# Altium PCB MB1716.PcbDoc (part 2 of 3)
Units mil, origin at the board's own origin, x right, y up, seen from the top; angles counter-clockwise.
Board outline 2806.95 x 1299.21 mil, 4 copper layers (Top Layer, M1, M2, Bottom Layer), stack 62.205 mil thick; 53 components, 45 nets, 298 pads, 399 vias.
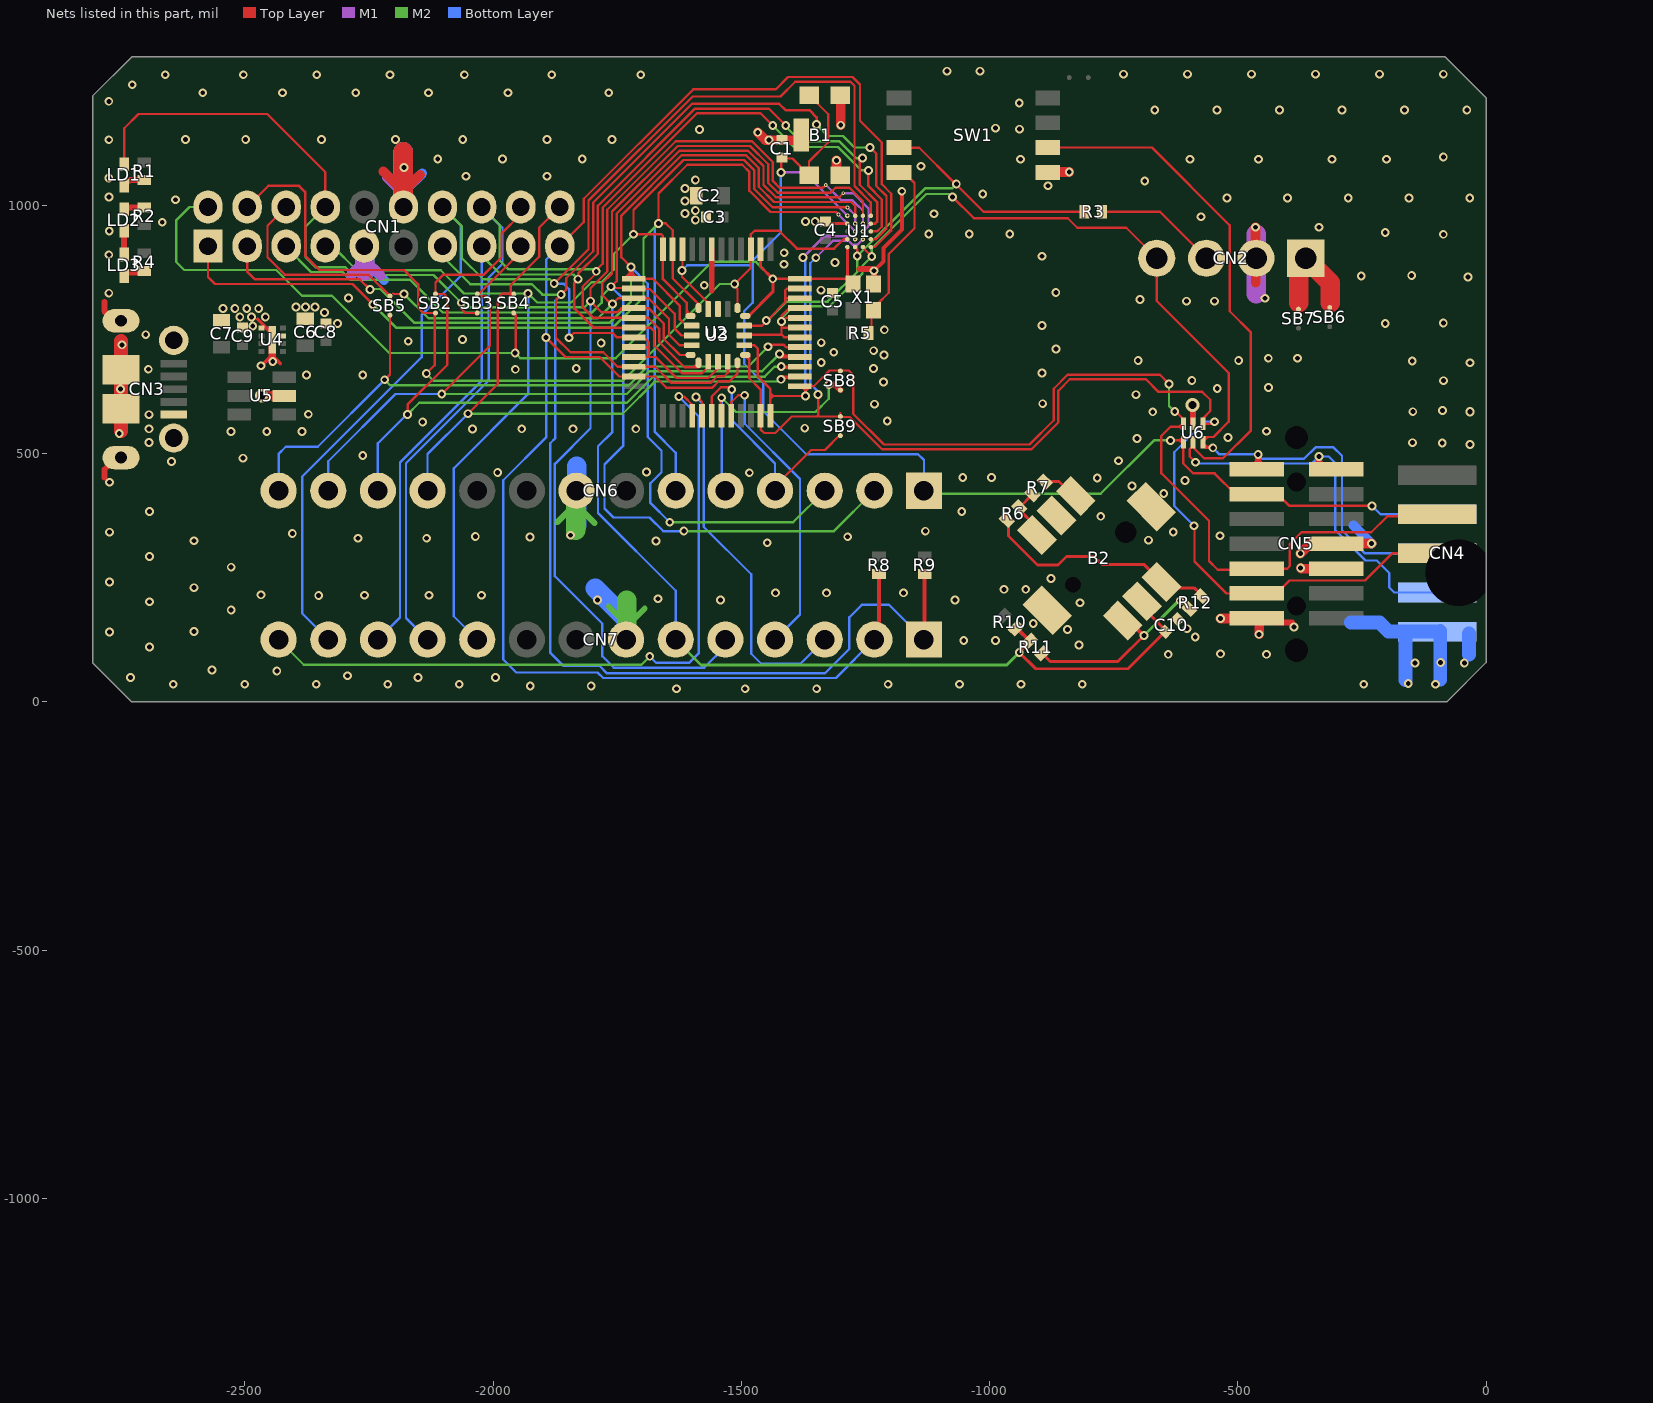
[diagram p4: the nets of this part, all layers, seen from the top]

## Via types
v1: diameter 17.72, hole 9.84, Top Layer to Bottom Layer, tented both sides, 357 vias
v2: diameter 27.56, hole 15.75, Top Layer to Bottom Layer, tented both sides, 31 vias
v3: diameter 7.87, hole 3.94, Top Layer to M1, tented both sides, 11 vias

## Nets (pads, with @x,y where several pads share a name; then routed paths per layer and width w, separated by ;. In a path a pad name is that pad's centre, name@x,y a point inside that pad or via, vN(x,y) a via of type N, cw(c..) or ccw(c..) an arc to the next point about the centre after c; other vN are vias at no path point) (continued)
GND: B1.2 B1.4 B1.5 B2.5 B2.7 B2.8 C1.1 C2.1 C3.1 C4.1 C5.1 C6.1 C7.1 C8.1 C9.1 C10.1 CN1.5 CN1.16 CN2.2 CN3.5 CN3.6 CN3.7 CN3.8 CN3.9 CN3.10 CN3.11 CN4.6 CN5.2 CN5.5 CN5.7 CN6.8 CN7.7 LD2.2 LD3.2 SW1.1 U1.D4 U2.7 U3.3 U4.3 U4.5 U4.9 U5.2 U6.2 X1.2 | length 3708.1
  Top Layer w5.91: C4.1@-1330.32,973.03 -1330.32,963.48 U1.D4@-1286.59,963.48 ; v2(-591.38,598.03) v2@-590.11,596.77
  Top Layer w7.28: -2474.29,770.83 U4.9@-2443.49,740.02 ; v1@-2463.23,680.59 -2443.13,700.69 ; -2449.1,701.81 -2429,681.71
  Top Layer w7.87: v1(-1232.95,868.5) -1214.09,887.36 -1214.09,914.29 -1176.85,951.54 v1(-1176.85,1028.7)
  Top Layer w11.81: -2783.27,806.1 -2783.27,787.15 CN3.9@-2763.04,766.92 ; -2783.19,451.5 -2783.19,468.23 -2761.86,489.56 CN3.8@-2761.86,494.61 ; LD3.2@-2744.06,901.34 LD2.2@-2744.06,949.25 ; -1559.76,828.7 U2.7@-1559.76,911.42 ; -1262.4,872.01 -1236.46,872.01 v1(-1232.95,868.5) X1.2@-1232.95,842.72 ; SW1.1@-882.75,1066.73 SW1.1@-881.93,1067.56 ; U6.2@-590.11,560.47 v2@-590.11,596.77 ; CN5.2@-422.67,160.16 -390.35,160.16
  Top Layer w15.75: v1@-2445.16,684.65 U4.9@-2445.16,721.85
  Top Layer w19.68: v2(-2466.1,616.97) -2465.47,616.34 U5.2@-2420.79,616.34 ; -2221.4,1068.43 -2189.8,1036.84 ; CN1.16@-2178.67,1030.17 -2147.07,1061.77 ; v1(-1467.01,1147.32) -1451.3,1131.61 C1.1@-1418.23,1131.61 -1389.6,1131.61 B1.5@-1379.48,1141.73 ; v1(-1308.31,1090.98) -1308.31,1068.59 B1.4@-1300.74,1061.02 ; B1.2@-1300.74,1222.44 -1299.84,1221.54 v1(-1299.84,1161.73) ; X1.2@-1233.94,841.73 X1.2@-1232.95,842.72 ; SW1.1@-881.93,1067.56 v1(-839.57,1067.56) ; v1(-534.68,168.19) -462.14,168.19 CN5.2@-461.95,168.38 ; v1(-464.17,956.06) -463.99,844.12 ; v1(-457.05,136.06) CN5.2@-457.05,168.38 ; v1(-374.12,298.76) -374.12,299.35 -355.09,318.38 CN5.7@-301.95,318.38 -297.82,314.25 -293.05,319.02 v1(-230.59,319.02) ; v1(-373.39,269.65) -372.12,268.38 CN5.5@-301.95,268.38
  Top Layer w27.56: v1@-2749.86,545.16 v1@-2749.86,727.24
  Top Layer w39.37: CN1.16@-2180.77,989.43 -2180.77,1108.21
  M1 w19.68: -2286.97,859.43 CN1.5@-2255.37,891.03 ; CN1.5@-2258.04,890.14 -2226.44,858.54 ; -2213.83,1056.42 CN1.16@-2182.23,1024.82 ; CN1.16@-2184.9,1023.93 -2153.3,1055.53
  M1 w39.37: -2258.88,868.82 CN1.5@-2258.88,917.48 ; CN1.16@-2181.4,997.48 -2181.4,1046.14 ; -463.25,822.56 -463.25,942.36
  M2 w11.81: -1870.87,361.89 CN6.8@-1837.87,394.88 ; CN6.8@-1828.31,392.99 -1795.31,360 ; -1767.36,192.32 CN7.7@-1734.37,159.33 ; CN7.7@-1727.68,154.96 -1694.68,187.95
  M2 w39.37: CN1.16@-2180.77,996.85 -2180.77,1046.28 ; -1833.74,345.67 CN6.8@-1833.74,425.83 ; CN7.7@-1730.74,124.96 -1730.74,205.12
  Bottom Layer w19.68: -2286.97,859.43 CN1.5@-2255.37,891.03 ; -2251.79,881.42 -2220.19,849.82 ; -2207.53,1053.43 CN1.16@-2175.94,1021.83 ; -2174.37,1033.25 -2142.77,1064.85 ; -267.07,355.51 v1(-230.59,319.02)
  Bottom Layer w27.56: -272.48,159.88 -214.69,159.88 -196.45,141.65 CN4.6@-162.36,141.65 ; v1@-162.36,43.98 CN4.6@-162.36,141.65 ; CN4.6@-162.36,142.01 CN4.6@-162.36,141.65 ; CN4.6@-98.43,141.65 CN4.6@-162.36,141.65 ; -92.2,44.88 CN4.6@-92.2,142.91 ; -34.33,95.04 CN4.6@-34.33,138.35
  Bottom Layer w39.37: -2258.88,868.82 CN1.5@-2258.88,917.48 ; CN1.16@-2180.77,989.43 -2180.77,1108.21 ; -1832.03,355.73 -1832.03,474.5 ; -1794.01,228.72 -1732.24,166.94 CN7.7@-1732.24,125.39
  other v1: -1630.79,26.5 -1492.4,26.5 -1348.39,26.5 -1925.39,31.89 -1802.6,31.89 -2644.48,35.55 -2500.47,35.55 -2356.46,35.55 -2212.45,35.55 -2068.44,35.55 -1204.38,35.55 -1060.37,35.55 -936.92,35.55 -813.47,35.55 -246.34,35.55 -101.85,35.55 -156.73,37.17 -2730.91,49.29 -2151.77,49.29 -1995.51,49.29 -2293.27,52.64 -2435.87,62.4 -2566.73,64.33 -143.03,78.35 -91.34,79.17 -43.74,78.35 -640.12,95.76 -442.12,95.76 -534.68,96.76 -2692.2,110.67 -820.12,114.76 -1052.12,123.76 -988.12,123.76 -585.81,130.99 -2772.91,140.79 -2602.68,141.5 -843.12,145.76 -602.19,147.53 -387.12,150.76 -912.12,157.76 -2527.83,184.8 -818.12,199.76 -2692.2,201.67 -1789.65,205.12 -1541.85,205.12 -1069.61,205.12 -1667.76,207.87 -2351.57,214.45 -2259.37,214.88 -2129.37,214.88 -2023.78,214.88 -2467.64,215.63 -1431.26,219.68 -1328.74,219.68 -1173.66,219.68 -971.12,226.76 -927.12,226.76 -2602.68,230.12 -2772.91,241.35 -876.12,248.76 -2527.83,271.38 -2692.2,292.66 -1447.99,320.51 -1671.97,323.82 -2602.68,324.65 -680.12,325.76 -2272.32,329.72 -2134.06,329.72 -1926.06,332.13 -1285.94,332.6 -2035.98,333.31 -536.12,334.76 -1844.53,335.67 -2404.68,339.21 -2772.91,341.92 -630.12,342.04 -1129.49,343.94 -776.12,373.76 -2692.2,383.66 -1056.12,383.76 -649.12,419.76 -713.12,434.76 -2772.91,442.48 -606.12,445.76 -783.12,450.76 -1054.12,451.76 -996.12,451.76 -1991.02,461.89 -1484.06,461.54 -1690.94,462.99 -2648.15,484.49 -740.12,485.76 -2503.86,490.94 -2262.76,496.18 -32.52,518.54 -148.07,522.2 -88.07,521.61 -2693.15,522.52 -703.12,530.76 -520,532.68 -2753.19,540.79 -2528.12,544.76 -2456.22,544.88 -2385.12,544.88 -442.2,545.24 -2693.15,550.04 -2041.85,549.68 -1942.44,550.04 -1839.33,550.04 -1712.68,550.04 -1372.32,551.38 -2142.05,563.98 -1206.18,565.67 -2693.15,578.62 -2372.4,579.53 -671.34,584.29 -32.52,584.06 -147.44,584.65 -32.52,585.2 -87.8,587.13 -1232.05,599.72 -893.12,600.76 -705.04,618.9 -2750.71,630.55 -541.38,631.57 -437.95,633.23 -1213.62,644.37 -85.63,647.09 -592.64,647.68 -2375.91,658.31 -2262.87,658.54 -894.21,662.56 -2694.76,670 -1955.43,669.88 -1832.8,671.57 -1234.09,671.57 -2467.83,677.05 -32.52,683.07 -1339.25,683.66 -2444.06,685.55 -148.62,686.61 -700.75,687.64 -498.27,687.64 -438.5,692.24 -379.53,692.24 -1212.72,698.58 -1314.06,704.33 -1233.58,707.48 -866.1,710.91 -2747.68,719.25 -1782.52,722.76 -1339.25,723.58 -2171.22,726.57 -2062.01,730.28 -2700,739.76 -1212.09,749.45 -2484.33,757.36 -894.21,758.18 -202.99,762.24 -2313.78,762.48 -85.98,763.43 -2510.43,775.35 -2486.81,775.35 -2459.06,775.35 -2339.92,784.57 -2544.41,792.56 -2520.43,792.56 -2496.46,792.56 -2472.48,792.56 -2397.52,795.63 -2378.37,795.63 -2359.21,795.63 -603.62,807.2 -547.2,807.2 -697.01,810.71 -445.28,813.07 -2291.42,813.66 -2774.29,823.35 -866.57,824.68 -1339.8,829.37 -1574.92,839.37 -36.34,855.63 -251.46,857.99 -149.8,859.17 -1414.21,881.54 -1311.57,885.32 -894.21,897.64 -2774.29,900.63 -1413.88,904.8 -1122.52,942.24 -1040.94,942.24 -959.37,942.24 -85.98,941.89 -202.99,945.43 -2773.46,948.82 -336.54,956.06 -2666.65,966.3 -1370.98,967.6 -1351.38,967.6 -1592.8,970.67 -574.09,977.36 -1112.24,983.23 -1613.78,983.74 -1592.8,989.8 -1613.78,1009.06 -2640.04,1011.57 -522.09,1015.16 -399.76,1015.16 -277.44,1015.16 -155.12,1015.16 -32.8,1015.16 -2773.86,1016.93 -1013.94,1022.83 -1613.78,1034.37 -882.09,1039.84 -687.56,1049.45 -1592.8,1051.02 -2774.29,1055.2 -2055.04,1058.82 -1891.46,1058.82 -2179.57,1076.61 -1138.43,1078.98 -937.83,1093.11 -596.54,1093.15 -458.27,1093.15 -310.55,1093.15 -200.63,1093.15 -2111.65,1093.43 -1981.1,1093.43 -1820.67,1093.43 -85.98,1097.87 -1444.65,1132.13 -2774.29,1132.48 -2619.76,1132.72 -2498.62,1132.72 -2346.06,1132.72 -2196.61,1132.72 -2061.34,1132.72 -1891.46,1132.72 -1760.87,1132.72 -1584.57,1153.23 -939.84,1153.74 -988.43,1155.75 -667.44,1192.44 -541.69,1192.44 -415.94,1192.44 -290.2,1192.44 -164.45,1192.44 -38.7,1192.44 -940.32,1206.38 -2774.29,1209.76 -2585.16,1227.13 -2424.68,1227.13 -2276.81,1227.13 -2130.55,1227.13 -1970.08,1227.13 -1767.17,1227.13 -2727.01,1243.11 -2660.67,1263.31 -2503.35,1263.31 -2355.47,1263.31 -2207.6,1263.31 -2058.19,1263.31 -1882.01,1263.31 -1702.68,1263.31 -730.08,1264.53 -601.26,1264.53 -472.44,1264.53 -343.62,1264.53 -214.8,1264.53 -85.98,1264.53 -1085.71,1270.55 -1019.53,1270.55
NetB2_1: B2.1 R11.2 R12.1 | length 419.5
  Top Layer w5.91: R11.2@-894.06,97.71 -878.12,81.76 -741.12,81.76 v1(-689.12,133.76) v1@-690.12,133.76 ; B2.1@-732.52,171.28 -732.52,170.76 B2.1@-727.12,170.76 ; v1(-616.12,203.76) -614.23,203.76 R12.1@-597.79,187.32
  Top Layer w7.87: B2.1@-727.12,170.76 v1@-690.12,133.76
  M2 w5.91: v1(-689.12,133.76) -619.12,203.76 v1(-616.12,203.76)
NetB2_3: B2.3 R6.1 R12.2 | length 455.7
  Top Layer w5.91: R6.1@-965.04,366.76 -962.12,363.84 -962.12,334.42 -903.45,275.76 -862.02,275.76 -845.12,292.66 -789.12,292.66 -772.87,276.41 -688.37,276.41 B2.3@-653.78,241.82 ; B2.3@-635.62,229.76 -587.87,229.76 R12.2@-578.21,220.1
NetB2_4: B2.4 R6.2 R7.1 | length 106.3
  Top Layer w5.91: R6.2@-942.52,389.27 -904.33,351.08 B2.4@-904.33,336.48 ; R6.2@-939.98,391.82 -914.12,417.68 R7.1@-914.12,418.76
NetB2_6: B2.6 R7.2 | length 67.2
  Top Layer w5.91: R7.2@-889.06,443.82 -860.17,443.82 B2.6@-833.12,416.76
NetCN2_1: CN2.1 SB6.2 SB7.1 | length 205.4
  Top Layer w7.87: SB6.2@-314.84,794.05 SB6.2@-314.84,794.25
  Top Layer w39.37: -377.28,804.37 -377.28,879.66 CN2.1@-363.25,893.7 -314.25,844.71 -314.25,803.9
NetCN2_3: CN2.3 R3.2 | length 252.3
  Top Layer w4.72: R3.2@-773.15,987.44 -656.99,987.44 CN2.3@-563.25,893.7
  M2 w4.72: CN2.3@-566.81,893.7 CN2.3@-563.25,893.7
NetLD1_1: LD1.1 R1.1 | length 45.1
  Top Layer w11.81: LD1.1@-2743.15,1039.8 -2731.73,1051.22 R1.1@-2702.75,1051.22
NetLD2_1: LD2.1 R2.1 | length 42.1
  Top Layer w7.87: LD2.1@-2743.15,992.22 LD2.1@-2739.11,996.26
  Top Layer w11.81: LD2.1@-2739.11,996.26 R2.1@-2702.75,996.26
NetLD3_1: LD3.1 R4.1 | length 44.7
  Top Layer w11.81: LD3.1@-2743.15,858.03 -2736.14,865.04 -2706.02,865.04 R4.1@-2702.75,868.31
NRST: B1.1 B1.3 C1.2 CN4.9 CN5.12 CN6.1 U1.E4 U2.10 U3.4 U6.4 | length 2900.1
  Top Layer w4.72: v1(-1619.61,869.06) -1619.61,856.26 -1566.93,803.58 U3.4@-1566.93,791.34 ; v1@-1618.81,869.06 U2.10@-1618.81,911.42 ; v1(-1420.51,1066.69) -1419.76,1067.44 -1419.76,1094.61 -1397.32,1094.61 B1.3@-1363.74,1061.02 -1363.74,1088.82 -1325.24,1127.32 -1325.24,1183.94 B1.1@-1363.74,1222.44 ; v1(-635.62,526.76) -617.57,526.76 ; -617.72,526.61 -617.57,526.76 ; -617.16,526.14 U6.4@-611.54,520.51 ; U6.4@-612.09,532.24 -617.57,526.76 ; v1(-229.68,394.84) -396.1,394.84 -419.64,418.38 CN5.12@-461.95,418.38 -504.8,418.38 -546.69,460.28 -589.65,460.28 -609.84,480.47 -609.84,523.03 U6.4@-609.8,523.07 -613.49,526.76 -617.57,526.76
  M1 w4.72: v1(-1420.51,1066.69) -1373.54,1066.69 v3(-1286.61,979.76)
  M2 w4.72: CN6.1@-1132.24,425.39 -1126.37,419.53 -776.14,419.53 -668.91,526.76 v1(-635.62,526.76)
  Bottom Layer w4.72: v1(-1619.61,869.06) -1609.06,879.61 -1481.93,879.61 ; -1477.32,875 -1481.93,879.61 ; -1477.32,884.21 -1481.93,879.61 ; v1(-1420.51,1066.69) -1420.51,945.87 -1477.15,889.23 -1477.15,879.61 ; CN6.1@-1132.24,425.39 -1132.24,486.96 -1144.25,498.98 -1369.25,498.98 -1455.91,585.63 -1455.91,642.68 -1494.37,681.14 -1494.37,787.13 -1477.15,804.35 -1477.15,879.61 ; v1(-229.68,394.84) -212.71,377.87 CN4.9@-98.43,377.87 ; -1481.93,879.61 -1477.15,879.61
OSC32K_EN: R5.1 SW1.8 X1.1 | length 379.5
  Top Layer w4.72: R5.1@-1237.91,745.28 -1237.91,777.36 -1231.97,783.31 -1226.57,783.31 -1226.57,800.79 -1203.07,824.29 -1203.07,902.36 -1151.18,954.25 -1151.18,1045.28 -1172.64,1066.73 SW1.8@-1182.75,1066.73
PA0: CN1.1 CN6.6 U1.C3 U2.11 U3.5 | length 2498.3
  Top Layer w4.72: CN1.1@-2574.47,918.11 -2574.47,855.65 -2560.51,841.69 -2283.5,841.69 v1(-2242.17,800.35) ; U3.5@-1586.61,793.31 -1586.61,801.3 -1638.5,853.19 U2.11@-1638.5,911.42 -1638.5,949.92 -1652.44,963.86 v1(-1667.01,963.86) -1667.01,1024.33 -1609.25,1082.09 -1498.46,1082.09 -1483.9,1067.52 -1483.9,1029.76 -1441.1,986.97 -1309.41,986.97 v3(-1304.61,982.17)
  M1 w4.72: v3(-1304.61,982.17) -1304.61,981.5 v3(-1270.84,947.74)
  M2 w4.72: v1(-2242.17,800.35) -2195.79,753.98 -1758.62,753.98 -1697.32,815.28 -1697.32,933.54 v1(-1667.01,963.86)
  Bottom Layer w4.72: v1(-1667.01,963.86) -1674.33,956.54 -1674.33,543.7 -1632.24,501.61 CN6.6@-1632.24,425.39
PA1: CN1.4 CN7.10 U1.D3 U2.12 U3.6 | length 2403.3
  Top Layer w4.72: CN1.4@-2338.25,918.11 CN1.4@-2338.07,918.11 ; -1609.43,787.05 U3.6@-1602.54,780.16 ; U3.6@-1602.36,777.56 -1608.82,777.56 -1610.24,778.98 -1610.24,803.7 -1658.18,851.65 U2.12@-1658.18,911.42 -1658.18,938.85 -1661.38,942.05 v1(-1717.44,942.05) -1717.44,990.75 -1616.65,1091.54 -1494.55,1091.54 -1474.45,1071.43 -1474.45,1033.68 -1437.19,996.42 -1286.5,996.42 v3(-1286.5,996.02)
  M1 w4.72: v3(-1286.5,996.02) -1270.84,980.37 v3(-1270.84,963.48)
  M2 w4.72: CN1.4@-2338.25,918.11 -2323.56,918.11 -2274.98,869.53 -2105.79,869.53 -2059.06,822.8 v1(-1929.68,822.8) -1911.38,804.49 -1842.95,804.49 -1801.94,845.5 -1782.26,845.5 -1757.17,870.59 -1757.17,902.32 v1(-1717.44,942.05)
  Bottom Layer w4.72: CN7.10@-2032.24,125.39 -2079.29,172.44 -2079.29,470.4 -1929.68,620 v1(-1929.68,822.8)
PA2: CN1.2 CN6.3 U1.E3 U2.13 U3.7 | length 2848.3
  Top Layer w4.72: CN1.2@-2495.73,918.11 -2495.73,867.14 -2479.72,851.14 -2268.98,851.14 v1(-2248.39,830.55) ; U2.13@-1734.51,854.06 -1725.31,863.25 ; U2.13@-1725.31,854.91 -1725.31,863.25 ; v1@-1725.31,873.54 -1725.31,863.25 ; -1722.36,866.4 -1722.26,866.3 ; -1721.33,867.24 -1722.26,866.3 ; U2.13@-1718.74,854.75 -1718.74,862.78 ; v1@-1718.74,873.38 -1718.74,862.78 ; U2.13@-1709.18,853.22 -1718.74,862.78 ; U3.7@-1600.39,757.87 -1611.12,757.87 -1624.43,771.18 -1624.43,798.56 -1678.23,852.36 U2.13@-1717.24,852.36 -1722.56,857.68 -1722.56,866.01 ; U1.E3@-1270.84,979.23 -1270.84,998.99 -1278.9,1007.05 -1434.46,1007.05 -1465,1037.59 -1465,1075.35 -1490.64,1100.98 -1620.57,1100.98 -1741.81,979.74 -1741.81,895.57 v1(-1722.56,876.32) -1722.56,866.01 ; -1725.31,863.25 -1722.56,866.01 ; -1722.56,866.01 -1722.26,866.3 ; -1722.26,866.3 -1718.74,862.78
  M2 w4.72: v1@-2248.39,831.73 -2227.01,831.73 -2158.7,763.43 -1765.75,763.43 -1722.56,806.61 v1(-1722.56,876.32) ; v1(-1644.25,361.81) -1395.82,361.81 CN6.3@-1332.24,425.39
  Bottom Layer w4.72: v1(-1722.56,876.32) -1688.74,842.49 -1688.74,533.46 -1661.1,505.83 -1661.1,462.67 -1683.31,440.47 -1683.31,400.87 v1(-1644.25,361.81)
PA3: CN1.3 CN6.2 U1.C2 U2.14 U3.8 | length 2868.6
  Top Layer w4.72: U3.8@-1600.39,738.19 -1620.51,738.19 -1634.57,752.24 -1634.57,781.69 -1684.57,831.69 -1716.26,831.69 U2.14@-1717.24,832.68 -1718.46,833.9 -1759.88,833.9 v1(-1762.44,836.46) -1751.26,847.64 -1751.26,983.65 -1624.48,1110.43 -1486.72,1110.43 -1455.55,1079.26 -1455.55,1041.5 -1430.54,1016.5 -1303.07,1016.5 v3(-1294.88,1024.68)
  M1 w4.72: v3(-1294.88,1024.68) -1274.84,1024.68 -1244.07,993.91 -1244.07,958.76 v3(-1255.09,947.74)
  M2 w4.72: CN1.3@-2416.99,918.11 -2416.99,916.27 -2366.74,866.02 -2303.82,866.02 -2288.43,850.63 -2167.64,850.63 -2101.46,784.45 -1801.19,784.45 -1781.66,803.98 -1781.66,817.24 v1(-1762.44,836.46) ; v1(-1615.98,344.06) -1313.58,344.06 CN6.2@-1232.24,425.39
  Bottom Layer w4.72: v1(-1762.44,836.46) -1737.76,811.77 -1737.76,516.22 -1775.74,478.23 -1775.74,389.66 -1757.62,371.54 -1685.04,371.54 -1657.56,344.06 v1(-1615.98,344.06)
PA4: B2.2 C10.2 CN1.13 CN7.6 R10.2 R11.1 SB5.1 U1.E2 U2.15 U3.9 | length 3935.3
  Top Layer w4.72: CN1.13@-2416.99,996.85 -2454.68,959.15 -2454.68,895.71 -2419.57,860.59 -2251.06,860.59 SB5.1@-2208.03,817.56 ; -2201.26,822.72 -2200.35,821.81 v1(-2179.41,821.81) ; U3.9@-1600.39,718.5 -1624.8,718.5 -1645.71,739.41 -1645.71,771.73 -1686.97,812.99 U2.15@-1717.24,812.99 -1748.7,812.99 v1(-1759.92,801.77) -1762.44,801.77 -1780.47,819.8 -1780.47,843.43 -1760.71,863.19 -1760.71,987.57 -1628.39,1119.88 -1482.81,1119.88 -1446.1,1083.17 -1446.1,1045.42 -1426.63,1025.94 -1320.35,1025.94 -1310.59,1035.71 -1282.28,1035.71 -1255.09,1008.52 U1.E2@-1255.09,979.23 ; B2.2@-693.55,192.19 B2.2@-693.55,209.73 ; C10.2@-650.19,143.99 C10.2@-650.19,148.84
  Top Layer w5.91: R10.2@-946.84,148.23 R10.2@-944.59,148.23 ; v1@-940.12,101.76 v1(-940.12,99.76) -907.12,66.76 -721.11,66.76 C10.2@-647.03,140.84 ; B2.2@-693.55,192.19 C10.2@-650.19,148.84 ; C10.2@-650.19,143.99 C10.2@-647.04,140.84 ; C10.2@-646.34,141.53 C10.2@-647.03,140.84
  Top Layer w7.87: R10.2@-944.59,148.23 R11.1@-919.12,122.76 v1@-940.12,101.76
  M2 w4.72: v1(-2179.41,821.81) -2130.47,772.87 -1788.82,772.87 v1(-1759.92,801.77)
  M2 w5.91: CN7.6@-1632.24,125.39 -1581.43,74.59 -965.29,74.59 v1(-940.12,99.76)
  Bottom Layer w4.72: v1(-1759.92,801.77) -1759.92,543.78 -1788.74,514.96 -1788.74,380.47 -1632.24,223.97 CN7.6@-1632.24,125.39
PA5: CN1.14 CN7.5 LD1.2 SB3.1 U1.D2 U2.16 U3.10 | length 3655.8
  Top Layer w4.72: LD1.2@-2743.15,1083.11 -2743.15,1155.75 -2714.76,1184.13 -2455.12,1184.13 -2338.25,1067.26 CN1.14@-2338.25,996.85 ; v1(-2064.25,803.98) -2064.25,792.09 -2055.55,783.39 SB3.1@-2036.89,783.39 ; -1745.35,790 -1745.23,790 ; U2.16@-1717.32,790 -1745.23,790 ; U3.10@-1602.36,698.82 -1623.98,698.82 -1656.38,731.22 -1656.38,762.28 -1687.4,793.31 U2.16@-1717.24,793.31 -1741.93,793.31 -1745.23,790 ; v3(-1330.12,1041.65) -1336.38,1035.39 -1422.72,1035.39 -1436.65,1049.33 -1436.65,1087.09 -1478.9,1129.33 -1632.31,1129.33 -1770.16,991.48 -1770.16,867.17 -1803.9,833.43 v1(-1803.9,807.2) -1781.54,784.84 -1750.39,784.84 -1745.23,790 ; SB3.1@-2036.89,783.39 -2034.49,780.98 SB3.1@-2032.09,783.39 SB3.1@-2036.89,783.39
  M1 w4.72: v3(-1330.12,1041.65) -1299.43,1010.97 -1276.71,1010.97 -1263.07,997.32 -1262.76,997.32 -1255.09,989.66 v3(-1255.09,963.48)
  M2 w4.72: CN1.14@-2338.25,996.85 -2378.15,956.95 -2378.15,895.79 -2357.83,875.47 -2297.6,875.47 -2282.2,860.08 -2120.35,860.08 v1(-2064.25,803.98) -2055.32,795.04 -1816.06,795.04 v1(-1803.9,807.2)
  Bottom Layer w4.72: v1(-1803.9,807.2) -1803.9,551.3 -1875.74,479.45 -1875.74,252.95 -1780,157.2 -1780,92.01 -1757.05,69.06 -1574.88,69.06 -1532.24,111.7 CN7.5@-1532.24,125.39
PA6: CN1.18 CN7.11 U1.C1 U2.17 U3.11 | length 2660.4
  Top Layer w4.72: -1596.1,674.31 U3.11@-1589.21,681.2 ; U3.11@-1586.61,683.07 -1586.61,674.17 -1614.61,674.17 -1665.83,725.39 -1665.83,751.61 -1687.83,773.62 U2.17@-1717.24,773.62 -1798.03,773.62 -1819.84,795.43 -1819.84,836.1 -1792.52,863.43 v1(-1792.52,867.36) -1792.52,869.88 -1779.61,882.8 -1779.61,995.4 -1589.33,1185.67 -1461.65,1185.67 v1(-1436.93,1160.94) ; v1(-1244.17,1070.71) -1244.17,1039.09 -1217.17,1012.09 -1217.17,957.32 -1226.75,947.74 U1.C1@-1239.35,947.74
  M2 w4.72: CN1.18@-2023.28,996.85 -1986.5,960.06 -1986.5,888.7 -1969.07,871.28 -1796.44,871.28 v1(-1792.52,867.36) ; v1(-1436.93,1160.94) -1393.82,1117.83 -1305.24,1117.83 -1258.11,1070.71 v1(-1244.17,1070.71)
  Bottom Layer w4.72: CN7.11@-2132.24,125.39 -2175.74,168.9 -2175.74,480.54 -2009.04,647.25 -2009.04,854.6 -1981.16,882.48 -1981.16,954.72 CN1.18@-2023.28,996.85
PA7: CN1.8 CN7.12 U1.D1 U2.18 U3.12 | length 2512.2
  Top Layer w4.72: U3.12@-1566.93,685.04 -1568.54,683.42 -1568.54,673.03 -1579.39,662.19 -1619.82,662.19 -1676.06,718.43 -1676.06,746.97 -1683.03,753.94 U2.18@-1717.24,753.94 -1798.23,753.94 -1836.51,792.22 -1836.51,844 v1(-1828.98,851.54) -1828.98,862.95 -1789.06,902.87 -1789.06,999.31 -1593.25,1195.12 -1444.92,1195.12 v1(-1410.75,1160.94) v1@-1410.75,1158.98 ; v1(-1256.14,1095.39) -1259.92,1095.39 -1261.5,1093.82 -1261.5,1041.73 -1226.61,1006.85 -1226.61,967.52 -1230.65,963.48 U1.D1@-1239.35,963.48
  M2 w4.72: CN1.8@-2023.28,918.11 -2023.28,899.5 -1984.65,860.87 -1838.31,860.87 v1(-1828.98,851.54) ; v1@-1410.75,1158.98 -1381.38,1129.61 -1303.19,1129.61 -1268.98,1095.39 v1(-1256.14,1095.39)
  Bottom Layer w4.72: CN7.12@-2232.24,125.39 -2187.68,169.96 -2187.68,481.97 -2023.28,646.36 CN1.8@-2023.28,918.11
PA8: CN7.14 U2.28 | length 1505.1
  Top Layer w4.72: v1(-1626.06,615.28) -1615.87,615.28 -1599.13,598.54 U2.28@-1599.13,576.77 ; U2.28@-1602.67,573.5 -1602.67,601.53
  M2 w4.72: CN7.14@-2432.24,125.39 -2381.81,74.96 -1701.5,74.96 v1(-1684.72,91.73)
  Bottom Layer w4.72: v1(-1684.72,91.73) -1671.5,78.5 -1605.32,78.5 -1586.18,97.64 -1586.18,575.39 v1(-1626.06,615.28)
PA9: CN7.3 U2.29 | length 783.7
  Top Layer w4.72: v1(-1591.68,614.01) -1588.66,614.01 -1579.44,604.8 U2.29@-1579.44,576.77
  Bottom Layer w4.72: v1(-1591.68,614.01) -1575.74,598.07 -1575.74,352.4 -1480.35,257.01 -1480.35,97.13 -1460.08,76.85 -1380.78,76.85 CN7.3@-1332.24,125.39
PA10: CN7.4 U2.32 | length 618.8
  Top Layer w4.72: U2.32@-1520.39,576.77 -1520.39,603.43 -1506.22,617.6 v1(-1493.39,617.6)
  Bottom Layer w4.72: v1(-1493.39,617.6) -1493.39,560.24 -1381.89,448.74 -1381.89,175.74 CN7.4@-1432.24,125.39
PA11: CN1.7 CN7.1 R9.1 U1.B1 U2.22 U3.14 | length 3671.5
  Top Layer w4.72: U3.14@-1527.56,685.04 -1527.56,662.92 -1534.45,656.02 -1548.69,656.02 -1562.12,642.6 -1640.98,642.6 -1673.58,675.2 U2.22@-1717.24,675.2 -1749.37,675.2 -1778.33,704.15 -1844.35,704.15 -1873.39,733.19 -1873.39,810.12 v1(-1863.07,820.43) -1852.99,830.51 -1852.99,853.23 -1798.5,907.72 -1798.5,1005.83 -1599.45,1204.88 -1424.02,1204.88 -1411.18,1192.05 -1363.11,1192.05 -1348.46,1177.4 v1(-1348.46,1162.99) ; v1(-1240.71,1116.89) -1228.23,1104.41 -1228.23,1039.53 -1207.72,1019.02 -1207.72,953.41 -1229.14,931.99 U1.B1@-1239.35,931.99
  Top Layer w7.87: CN7.1@-1132.24,125.39 -1130.78,126.85 R9.1@-1130.78,257.32 R9.1@-1130.78,259.96
  M2 w4.72: CN1.7@-2102.03,918.11 -2102.03,897.58 -2045.94,841.5 -1921.97,841.5 -1900.91,820.43 v1(-1863.07,820.43) ; v1(-1348.46,1162.99) -1325.39,1139.92 -1295.32,1139.92 -1272.28,1116.89 v1(-1240.71,1116.89)
  Bottom Layer w4.72: v1(-1863.07,820.43) -1874.8,808.7 -1874.8,531.54 -1885.19,521.15 -1885.19,249.03 -1884.8,248.65 -1884.8,98.43 -1859.41,73.03 -1786.26,73.03 -1770.67,57.44 -1331.93,57.44 -1282.48,106.89 -1282.48,170.47 -1257.24,195.71 -1202.55,195.71 CN7.1@-1132.24,125.39
PA12: CN1.10 CN7.2 R8.1 U1.A1 U2.23 U3.15 | length 3434.7
  Top Layer w4.72: v1(-1893.39,733.78) -1854.25,694.65 -1785.28,694.65 -1746.14,655.51 U2.23@-1717.24,655.51 -1673.7,655.51 -1651.34,633.15 -1558.21,633.15 -1545.57,645.79 -1523.9,645.79 -1507.87,661.82 U3.15@-1507.87,683.07 ; CN1.10@-1865.8,909.23 CN1.10@-1865.8,918.11 -1817.4,966.51 -1817.4,1013.65 -1596.77,1234.29 -1430.48,1234.29 -1406.02,1258.74 -1276.26,1258.74 -1261.18,1243.66 -1261.18,1170.67 -1217.44,1126.93 -1217.44,1042.95 -1198.27,1023.78 -1198.27,949.37 -1231.4,916.24 U1.A1@-1239.35,916.24
  Top Layer w7.87: CN7.2@-1232.24,125.39 -1222.79,134.84 R8.1@-1222.79,257.32
  Bottom Layer w4.72: CN1.10@-1865.8,918.11 -1893.39,890.53 v1(-1893.39,733.78) -1893.39,532.72 -1979.72,446.38 -1979.72,85.43 -1953.5,59.21 -1789.61,59.21 -1778.39,47.99 -1309.64,47.99 CN7.2@-1232.24,125.39
PA13: CN4.3 CN5.4 SB9.1 U1.B2 U2.35 U3.16 U6.1 | length 2656.6
  Top Layer w4.72: U3.16@-1492.12,698.82 -1484.13,698.82 -1484.13,651.91 -1461.33,629.11 U2.35@-1461.33,576.77 -1461.33,549.01 -1454.13,541.81 -1431.77,541.81 -1398.74,574.84 -1348.23,574.84 ; U3.16@-1491.48,696.34 -1484.59,689.45 ; v1(-1345.51,619.17) -1345.51,577.56 -1348.23,574.84 ; -1301.33,581.43 -1301.1,581.46 ; SB9.1@-1300.55,574.84 -1348.23,574.84 ; -1295.51,573.98 -1281.81,573.98 -1216.77,508.94 -915.8,508.94 -861.42,563.32 -861.42,626.85 -838.5,649.76 -684.92,649.76 -659.65,624.49 -571.69,624.49 -555.71,608.5 -555.71,585.83 -570.43,571.11 U6.1@-570.43,560.47 -551.02,560.47 v1(-547.17,564.33) ; v1(-588.12,354.76) -587.12,353.76 -587.12,282.95 -522.55,218.38 CN5.4@-461.95,218.38 -422.09,218.38 -395.98,244.49 -243.94,244.49 -189.29,299.13 CN4.3@-98.43,299.13
  M1 w4.72: v1(-1350.08,894.68) -1316.06,928.7 -1283.74,928.7 -1276,920.96 -1266.12,920.96 v3(-1255.09,931.99)
  Bottom Layer w4.72: v1(-1350.08,894.68) -1361.14,883.62 -1361.14,640.83 -1346.66,626.35 -1346.66,618.02 v1(-1345.51,619.17) ; v1(-588.12,354.76) -628.23,394.87 -628.23,502.87 -566.77,564.33 v1(-547.17,564.33)
PA14: CN4.4 CN5.6 SB8.1 U1.B3 U2.36 U2.37 U3.17 U6.3 | length 2671.2
  Top Layer w4.72: U3.17@-1494.09,718.5 -1473.74,718.5 -1466.77,711.54 -1466.77,655.43 -1441.65,630.31 U2.36@-1441.65,576.77 ; -1440.71,611.25 -1435.86,616.1 ; -1440.71,620.94 -1435.86,616.1 ; -1440.47,616.1 -1435.86,616.1 ; U2.37@-1382.59,635.83 U2.37@-1379.86,635.83 ; U2.37@-1381.23,637.19 U2.37@-1379.86,635.83 ; -1370.94,626.91 -1371.12,627.08 ; -1369.87,626.72 U2.37@-1360.76,635.83 ; v1(-638.58,640.51) -657.28,659.21 -842.42,659.21 -870.87,630.76 -870.87,567.23 -919.71,518.39 -1212.86,518.39 -1274.65,580.17 -1274.65,658.5 -1283.7,667.56 -1322.4,667.56 -1354.13,635.83 U2.37@-1360.76,635.83 ; v1@-625.89,585.81 -609.8,569.72 U6.3@-609.8,560.47 -609.8,553.11 -610.86,554.17 -635.71,554.17 -654.12,535.76 -654.12,460.85 -558.1,364.83 -558.1,283.75 -540.54,266.18 CN5.6@-473.74,266.18 ; -617.63,554.45 U6.3@-612.01,560.08 ; -616.06,553.19 U6.3@-613.01,550.14 ; CN5.6@-461.95,268.38 -400.6,268.38 -395.28,273.7 -395.28,318.1 -371.76,341.61 -231.22,341.61 -199.09,373.74 -173.97,373.74 -164.17,363.94 -150.23,377.87 CN4.4@-98.43,377.87 ; -1435.86,616.1 v1(-1371.12,616.1) -1371.12,627.08 ; U2.37@-1379.86,635.83 -1371.12,627.08 ; U2.37@-1379.86,635.83 U2.37@-1371.12,635.83 ; -1371.12,627.08 U2.37@-1371.12,635.83 ; U2.37@-1371.12,635.83 U2.37@-1360.76,635.83
  M1 w4.72: v1(-1375.79,895.2) -1332.68,938.31 -1277.16,938.31 v3(-1270.84,931.99)
  M2 w4.72: v1(-638.58,640.51) -638.58,596.26 v1(-627.01,584.68)
  Bottom Layer w4.72: v1(-1375.79,895.2) -1371.12,890.53 v1(-1371.12,616.1)
PB0: CN1.17 CN7.13 U1.E1 U2.19 U2.20 U2.21 U3.13 | length 3033.6
  Top Layer w4.72: v1(-1877.17,842.53) v1(-1877.17,842.53) -1807.95,911.69 -1807.95,1009.74 -1598.1,1219.59 -1421.39,1219.59 -1391.69,1249.29 -1280.17,1249.29 -1272.2,1241.33 -1272.2,1039.08 -1239.35,1006.22 U1.E1@-1239.35,979.23 ; v1(-1847.05,733.58) -1837.6,743.03 -1759.21,743.03 -1750.43,734.25 U2.19@-1717.24,734.25 -1696.3,734.25 -1686.34,724.29 -1686.34,695.04 ; U2.21@-1717.24,694.88 -1673.15,694.88 -1630.66,652.39 -1566.93,652.39 -1547.24,672.08 U3.13@-1547.24,685.04 ; U2.20@-1700.98,714.65 -1686.89,714.65
  M2 w4.72: CN1.17@-2102.03,996.85 -2063.7,958.53 -2063.7,894.8 -2020.12,851.22 -1885.86,851.22 v1(-1877.17,842.53)
  Bottom Layer w4.72: CN7.13@-2332.24,125.39 -2384.74,177.89 -2384.74,453.84 -2144.15,694.43 -2144.15,779.08 -2065.41,857.82 -2065.41,960.24 CN1.17@-2102.03,996.85 ; v1(-1877.17,842.53) -1858.2,842.53 -1847.05,831.38 v1(-1847.05,733.58)
PC6: CN6.4 SB9.2 U2.30 | length 511.3
  Top Layer w4.72: U2.30@-1559.76,576.77 -1559.76,615.27 -1541.45,633.58 -1523.58,633.58 v1(-1519.53,629.53) ; CN6.4@-1432.24,425.39 -1432.24,434.53 -1359.21,507.56 -1331.69,507.56 -1302.8,536.46 SB9.2@-1300.55,536.46
  Bottom Layer w4.72: v1(-1519.53,629.53) -1519.53,567.68 -1432.24,480.39 CN6.4@-1432.24,425.39
PC7: CN6.5 SB8.2 U2.31 | length 526.6
  Top Layer w4.72: U2.31@-1540.07,576.77 -1541.93,578.63 -1541.93,608.15 -1537.36,612.72 v1(-1539.76,612.72)
  Top Layer w11.81: v1(-1324.02,639.25) -1311.69,639.25 SB8.2@-1300.63,628.19
  M2 w4.72: v1(-1539.76,612.72) -1511.14,584.09 -1350.55,584.09 -1324.02,610.63 v1(-1324.02,639.25)
  Bottom Layer w4.72: v1(-1539.76,612.72) -1539.76,432.92 CN6.5@-1532.24,425.39
PC14: CN1.11 SB4.1 U1.A4 U2.2 U2.48 U3.20 X1.3 | length 2064.4
  Top Layer w4.72: SB4.1@-1958.5,783.39 -1954.37,779.25 v1@-1954.37,711.1
  Top Layer w5.91: U3.20@-1492.12,777.56 -1485.2,777.56 -1436.77,825.98 v1(-1436.77,852.24) v1@-1436.89,852.36 ; U2.2@-1461.33,911.42 -1461.33,876.81 v1@-1436.89,852.36 ; U1.A4@-1286.59,916.24 X1.3@-1286.59,852.36 ; X1.3@-1272.68,837.95 X1.3@-1272.68,839.53 ; v1@-1436.89,852.36 U2.48@-1382.59,852.36 X1.3@-1286.59,852.36 ; X1.3@-1286.59,852.36 -1278.89,852.36 -1286.59,844.66 X1.3@-1286.59,852.36 ; X1.3@-1272.68,839.53 -1281.46,839.53 -1286.34,844.41 -1267.8,844.41 X1.3@-1272.68,839.53
  M2 w4.72: CN1.11@-2574.47,996.85 -2611.69,996.85 -2638.82,969.72 -2638.82,886.46 -2622.28,869.92 -2436.85,869.92 -2384.96,818.03 -2324.68,818.03 -2209.49,702.83 v1(-1955.71,702.83) -1945.24,692.36 -1753.35,692.36 -1558.82,886.89 -1471.42,886.89 v1(-1436.77,852.24)
PC15: CN1.12 SB2.1 U1.B4 U2.3 U3.1 | length 1827.9
  Top Layer w4.72: CN1.12@-2495.73,996.85 -2453.13,1039.45 -2390.98,1039.45 -2378.86,1027.32 -2378.86,899.29 -2349.61,870.04 -2179.76,870.04 -2150.79,841.06 -2150.79,793.78 -2140.39,783.39 SB2.1@-2116.22,783.39 -2117.76,781.85 -2117.76,678.35 v1(-2134.72,661.38) ; U3.1@-1507.87,793.31 -1507.87,831.85 -1513.58,837.56 v1(-1513.58,841.77) -1481.02,874.33 U2.3@-1481.02,911.42 -1481.02,941.7 -1473.46,949.25 -1424.33,949.25 -1388.23,913.15 -1313.23,913.15 -1294.39,931.99 U1.B4@-1286.59,931.99
  M2 w4.72: v1(-2134.72,661.38) -2120.35,647.01 -1738.35,647.01 -1543.58,841.77 v1(-1513.58,841.77)
PD0: CN1.20 CN6.11 SB4.2 U2.38 | length 1448
  Top Layer w4.72: v1(-2050.83,580.59) -2050.55,580.59 -1990.71,640.43 -1990.71,813.39 -1981.97,822.13 -1964.68,822.13 ; -1964.68,815.87 -1964.68,822.13 ; CN1.20@-1865.8,996.85 -1907.48,955.17 -1907.48,896.73 -1964.68,839.53 -1964.68,822.13 ; v1@-1421.85,655.51 v1@-1415.39,655.51 ; v1(-1420.45,649.75) -1420.45,650.46 v1@-1418.46,652.44 ; v1@-1418.62,652.44 v1@-1418.46,652.44 ; v1@-1416.5,646.67 -1410.73,652.44 ; -1409.61,653.56 -1410.73,652.44 ; U2.38@-1385.82,652.44 -1410.73,652.44 ; U2.38@-1382.59,655.51 v1@-1415.39,655.51 ; v1@-1418.46,652.44 v1@-1415.39,655.51 ; v1@-1418.46,652.44 -1410.73,652.44
  M2 w4.72: v1(-2050.83,580.59) -1739.02,580.59 -1674.13,645.47 -1512.92,645.47 -1512.88,645.43 -1423.23,645.43 -1420.45,648.21 v1(-1420.45,649.75)
  Bottom Layer w4.72: CN6.11@-2132.24,425.39 -2132.24,499.18 v1(-2050.83,580.59)
PD1: CN1.19 CN6.12 SB2.2 U2.39 | length 1635.4
  Top Layer w4.72: v1(-2172.36,578.86) -2172.36,599.13 -2092.32,679.17 -2092.32,815.24 -2098.86,821.77 SB2.2@-2116.22,821.77 -2116.22,844.57 -2100,860.79 -2018.39,860.79 -1983.39,895.79 -1983.39,943.62 -1944.54,982.46 CN1.19@-1944.54,996.85 ; v1@-1419.66,672.83 U2.39@-1384.96,672.83 ; v1(-1419.66,675.36) -1387.48,675.36 U2.39@-1384.96,672.83 ; U2.39@-1382.59,675.2 U2.39@-1384.96,672.83
  M2 w4.72: v1(-2172.36,578.86) -2148.78,602.44 -1730.53,602.44 -1678.05,654.92 -1453.31,654.92 -1432.87,675.36 v1(-1419.66,675.36)
  Bottom Layer w4.72: CN6.12@-2232.24,425.39 -2232.24,520.87 v1@-2173.31,579.8
PD2: CN1.9 CN6.13 SB3.2 U2.40 | length 1527.6
  Top Layer w4.72: v1(-2103.58,620.28) -2006.46,717.4 -2006.46,808.46 -2015.43,817.44 -2024.02,817.44 ; SB3.2@-2032.09,821.77 -2029.11,821.77 -1944.54,906.34 CN1.9@-1944.54,918.11 ; v1(-1423.31,700.98) -1419.37,697.05 -1384.76,697.05 U2.40@-1382.59,694.88 ; v1@-1422.36,694.53 U2.40@-1389.56,694.53 ; v1@-1419.35,704.25 -1412.46,697.36
  M2 w4.72: v1(-2103.58,620.28) -1730.91,620.28 -1684.92,666.26 -1458.03,666.26 v1(-1423.31,700.98)
  Bottom Layer w4.72: CN6.13@-2332.24,425.39 -2332.24,484.65 -2196.61,620.28 v1(-2103.58,620.28)
PD3: CN6.14 SB5.2 U2.41 | length 1364.4
  Top Layer w4.72: v1@-2218.52,648.72 -2208.03,659.21 SB5.2@-2208.03,779.17 ; v1(-1446.69,715.35) -1442.28,719.76 -1415.16,719.76 -1409.96,714.57 U2.41@-1382.59,714.57
  M2 w4.72: v1(-2218.62,648.82) -2207.36,637.56 -1727.05,637.56 -1688.9,675.71 -1486.34,675.71 v1(-1446.69,715.35)
  Bottom Layer w4.72: CN6.14@-2432.24,425.39 -2432.24,499.65 -2417.99,513.9 -2353.54,513.9 v1@-2220.16,647.28 ; v1(-2218.62,648.82) v1@-2220.16,647.28 ; v1@-2217.09,647.28 v1@-2220.16,647.28
RX_DBG: CN4.7 CN5.13 SW1.2 U6.5 | length 1939.3
  Top Layer w4.72: SW1.2@-882.75,1116.73 -672.91,1116.73 -516.1,959.92 -516.1,786.81 -473.66,744.37 -473.66,546.85 -529.72,490.79 -567.99,490.79 -590.11,512.91 U6.5@-590.11,523.07 ; U6.5@-593.39,512.64 -597.09,508.94 -597.09,494.8 v1@-585.26,482.97 ; CN5.13@-351.77,472.73 -340.87,483.63 ; CN5.13@-340.87,472.96 -340.87,483.63 ; v1@-340.87,495.28 -340.87,483.63 ; CN5.13@-339.17,470.7 -339.17,485.32 ; v1@-339.17,493.03 -339.17,485.32 ; v1@-337.84,490.16 v1@-337.32,489.64 ; CN5.13@-337.32,472 v1@-337.32,487.17 ; v1@-337.32,494.33 v1@-337.32,489.64 ; v1@-336.58,485.43 -334.45,483.3 ; v1@-335.98,488.51 v1@-336.09,488.41 ; CN5.13@-334.45,471.57 -334.45,483.3 ; v1@-334.45,493.89 v1@-334.45,486.76 ; CN5.13@-332.56,473.55 CN5.13@-332.56,481.41 ; v1@-332.56,495.87 -332.56,484.87 ; CN5.13@-322.06,474.37 -332.56,484.87 ; CN5.13@-320.8,469.65 CN5.13@-332.56,481.41 ; -340.87,483.63 -339.17,485.32 ; -339.17,485.32 v1@-337.32,487.17 ; v1@-337.32,487.17 v1@-337.32,489.64 ; v1@-337.32,487.17 v1@-336.09,488.41 ; v1@-337.32,489.64 v1@-336.09,488.41 ; v1@-336.09,488.41 v1@-334.45,486.76 ; -334.45,483.3 CN5.13@-332.56,481.41 ; -334.45,483.3 v1@-334.45,486.76 ; v1@-334.45,486.76 -332.56,484.87 ; CN5.13@-332.56,481.41 -332.56,484.87
  Bottom Layer w4.72: v1(-585.47,482.76) -582.99,480.28 -350.55,480.28 v1(-336.61,494.21) -317.01,494.21 -303.5,480.71 -303.5,345.75 -242.52,284.76 -220.16,284.76 -195,259.61 -195,230.51 -184.88,220.39 CN4.7@-98.43,220.39
STM32_RX1: R3.1 SW1.7 U1.A3 U2.46 U2.47 U3.19 | length 1142.9
  Top Layer w4.72: U3.19@-1494.09,757.87 -1493.62,757.4 -1459.17,757.4 -1411.61,804.96 -1411.61,812.99 ; U2.46@-1382.59,812.99 -1411.61,812.99 ; U2.47@-1382.59,832.68 -1408.03,832.68 -1411.61,829.09 -1411.61,812.99 ; U1.A3@-1270.84,916.24 -1266.71,912.11 -1266.71,898.05 v1(-1266.61,897.95) ; SW1.7@-1182.75,1116.73 -1182.24,1116.22 -1141.73,1116.22 v1@-1071.75,1046.24 ; v1@-1067.09,1042.32 -1012.2,987.44 R3.1@-808.58,987.44
  M2 w4.72: v1(-1449.84,768.15) -1447.05,768.15 -1408.9,806.3 -1326.32,806.3 -1266.61,866 v1(-1266.61,897.95) -1130.16,1034.41 -1075.75,1034.41 v1(-1067.09,1043.07)
STM32_TX1: CN2.4 CN4.8 CN5.14 U1.A2 U2.42 U2.43 U2.44 U2.45 U3.18 U6.6 | length 2546.6
  Top Layer w4.72: U3.18@-1494.09,738.19 -1492.71,739.57 -1419.33,739.57 ; v1@-1419.17,766.14 v1(-1419.33,765.98) ; -1418.82,753.94 U2.43@-1382.59,753.94 ; v1@-1416.1,767.68 -1410.04,773.74 U2.44@-1374.09,773.74 ; U2.42@-1382.59,734.25 -1412.95,734.25 -1418.27,739.57 -1419.33,739.57 ; U2.45@-1382.59,793.31 -1403.15,793.31 -1419.33,777.13 v1(-1419.33,765.98) ; U1.A2@-1255.09,916.24 -1255.09,914.88 v1(-1237.36,897.14) ; v1(-1074.68,1017.32) -1031.63,974.27 -842.54,974.27 -823.54,955.28 -724.82,955.28 CN2.4@-663.25,893.7 -663.25,807.54 -518.27,662.56 -518.27,564.61 -549.29,533.58 -570.43,533.58 U6.6@-570.43,523.7 ; U6.6@-572.32,514.53 U6.6@-567.52,514.53 ; U6.6@-570.93,522.71 U6.6@-570.43,522.21 ; U6.6@-570.9,523.24 U6.6@-570.43,523.7 ; -560.74,512.52 -562.75,514.53 ; -560.71,533.43 U6.6@-570.43,523.7 ; v1@-557.91,514.53 -562.75,514.53 ; v1(-550.35,511.77) -564.76,511.77 U6.6@-567.52,514.53 ; CN5.14@-476.58,470.42 CN5.14@-470.28,476.72 ; CN5.14@-469.72,478.82 -462.64,485.91 ; CN5.14@-462.64,472.05 -462.64,484.36 ; v1@-462.64,495.46 -462.64,485.91 ; -462.08,486.47 -462.64,485.91 ; CN5.14@-461.95,468.38 -457.4,472.92 -459.33,474.85 -459.02,475.17 v1(-459.02,498.58) ; -460.03,486.98 -462.64,484.36 ; -457.49,488.39 -455.79,486.69 ; CN5.14@-455.79,471.85 -455.79,486.69 ; v1@-455.79,495.26 -455.79,486.69 ; CN5.14@-440.94,471.84 -449.71,480.61 -455.79,486.69 ; -1419.33,739.57 v1(-1419.33,765.98) ; U6.6@-570.43,522.21 U6.6@-570.43,523.07 U6.6@-570.43,523.7 ; U6.6@-570.43,522.21 -570.43,517.44 U6.6@-567.52,514.53 ; U6.6@-570.43,522.21 -562.75,514.53 ; U6.6@-567.52,514.53 -562.75,514.53 ; -462.64,484.36 -462.64,485.91
  M2 w4.72: v1@-1420.55,770.79 -1394.49,796.85 -1322.4,796.85 -1256.06,863.19 -1256.06,878.43 v1(-1237.36,897.14) -1237.36,913.35 -1127.6,1023.11 -1080.47,1023.11 v1(-1074.68,1017.32)
  Bottom Layer w4.72: v1(-550.35,511.77) -537.17,498.58 v1(-459.02,498.58) ; v1@-459.02,498.54 -459.33,498.23 -450.83,489.72 -366.54,489.72 -343.62,512.64 -307.13,512.64 -290.16,495.67 -290.16,345.76 -243.52,299.13 CN4.8@-98.43,299.13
